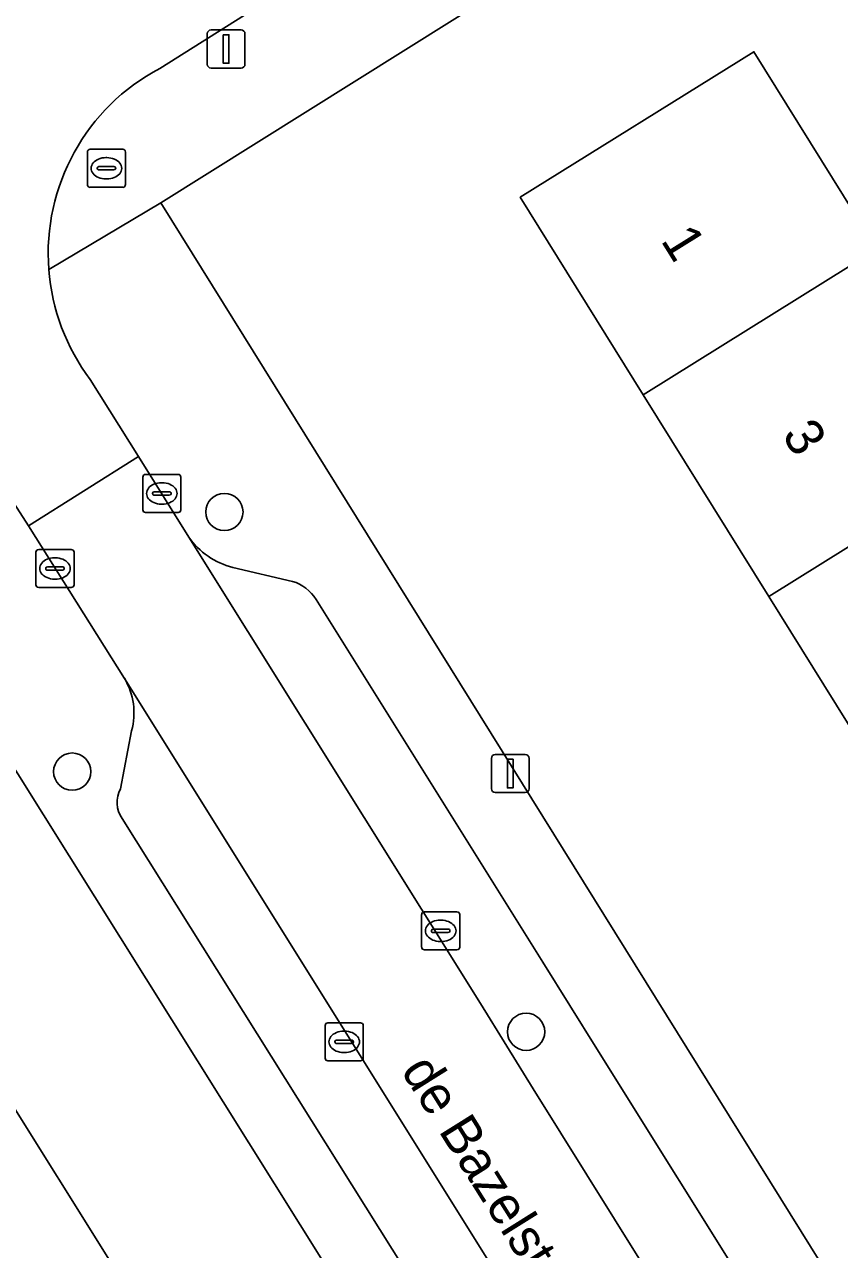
# Model space of a CAD drawing. Extents: x 159352 to 160617, y 385888 to 387323.
# Drawn here: x 159682.11 to 159703.51, y 386145.65 to 386177.82 of the extents above; entities that cross this region are included whole.
import ezdxf

# ---------------------------------------------------------------- set-up
doc = ezdxf.new("R2010")
doc.units = 0
for name, color, linetype in [('IMGEO_Boom', 7, 'Continuous'), ('IMGEO_Brandkraan', 7, 'Continuous'), ('IMGEO_Erf', 7, 'Continuous'), ('IMGEO_Kolk', 7, 'Continuous'), ('IMGEO_Lichtmast', 7, 'Continuous'), ('IMGEO_Openbare_ruimte_label', 7, 'Continuous'), ('IMGEO_Pand', 7, 'Continuous'), ('IMGEO_Pand_nummerreeks', 7, 'Continuous'), ('IMGEO_Parkeervlak_open', 7, 'Continuous'), ('IMGEO_Rijbaan_lokaal_open', 7, 'Continuous'), ('IMGEO_Voetpad_open', 7, 'Continuous')]:
    doc.layers.add(name, color=color, linetype=linetype)

msp = doc.modelspace()

# ---------------------------------------------------------------- linework, layer by layer
at = {"layer": 'IMGEO_Boom'}
for centre in [(159687.358, 386165.017), (159683.361, 386158.199), (159695.28, 386151.366)]:
    msp.add_circle(centre, 0.489, dxfattribs=at)
at = {"layer": 'IMGEO_Brandkraan'}
for p, q in [((159683.76, 386173.617), (159683.76, 386174.469)), ((159683.835, 386174.543), (159684.687, 386174.543)), ((159684.761, 386174.469), (159684.761, 386173.617)), ((159684.062, 386174.086), (159684.46, 386174.086)), ((159684.248, 386174.323), (159684.273, 386174.323)), ((159684.019, 386174.037), (159684.019, 386174.049)), ((159684.457, 386174), (159684.059, 386174)), ((159684.271, 386173.763), (159684.246, 386173.763)), ((159684.503, 386174.049), (159684.503, 386174.037)), ((159684.687, 386173.543), (159683.835, 386173.543))]:
    msp.add_line(p, q, dxfattribs=at)
for points in [[(159683.76, 386173.617), (159683.76, 386174.469)], [(159683.835, 386174.543), (159684.687, 386174.543)], [(159684.761, 386174.469), (159684.761, 386173.617)], [(159684.687, 386173.543), (159683.835, 386173.543)]]:
    msp.add_lwpolyline(points, dxfattribs=at)
for centre, radius, start, end in [((159683.837, 386174.467), 0.0765, 91.552, 178.448), ((159683.837, 386174.467), 0.0765, 91.552, 178.448), ((159684.685, 386174.467), 0.0765, 1.552, 88.448), ((159684.685, 386174.467), 0.0765, 1.552, 88.448), ((159684.059, 386174.046), 0.0403, 85.8775, 175.7526), ((159684.464, 386174.048), 0.0386, 1.7309, 96.639), ((159684.056, 386174.036), 0.0366, 178.938, 274.7102), ((159684.46, 386174.043), 0.043, 264.8664, 352.4533), ((159683.837, 386173.619), 0.0765, 181.552, 268.448), ((159683.837, 386173.619), 0.0765, 181.552, 268.448), ((159684.685, 386173.619), 0.0765, 271.552, 358.448), ((159684.685, 386173.619), 0.0765, 271.552, 358.448)]:
    msp.add_arc(centre, radius, start, end, dxfattribs=at)
for centre, major_axis, ratio, start_param, end_param in [((159684.247, 386174.043), (-0.387, 0.002), 0.722429, 4.712389, 7.853982), ((159684.272, 386174.043), (-0.39, 0.002), 0.717154, 1.570796, 4.712389)]:
    msp.add_ellipse(centre, major_axis=major_axis, ratio=ratio, start_param=start_param, end_param=end_param, dxfattribs=at)
at = {"layer": 'IMGEO_Erf'}
for points in [[(159733.216, 386143.666), (159731.929, 386145.722), (159730.642, 386147.777), (159733.744, 386149.721), (159730.165, 386155.842), (159726.781, 386153.737), (159725.367, 386156.01), (159722.148, 386161.186), (159725.532, 386163.291), (159723.428, 386166.327), (159720.325, 386164.383), (159719.037, 386166.44), (159717.751, 386168.494), (159720.853, 386170.438), (159718.998, 386173.467), (159715.904, 386171.529), (159712.527, 386176.922), (159715.626, 386178.852), (159715.021, 386179.818), (159711.398, 386177.548), (159706.136, 386185.947), (159685.685, 386173.135), (159722.272, 386114.357)], [(159704.872, 386157.62), (159701.649, 386162.8), (159698.354, 386168.096), (159695.125, 386173.284), (159701.262, 386177.103), (159703.904, 386172.858)], [(159712.934, 386108.61), (159677.208, 386165.677), (159674.448, 386166.054), (159663.861, 386159.423), (159663.923, 386159.326), (159657.127, 386155.101), (159662.969, 386145.784), (159661.381, 386144.772)], [(159678.55, 386141.18), (159675.326, 386146.356), (159673.029, 386144.926), (159671.294, 386147.714), (159673.587, 386149.149), (159672.103, 386151.532), (159669.661, 386150.002), (159664.466, 386158.268), (159669.886, 386161.642), (159671.796, 386158.603), (159674.849, 386160.506), (159675.173, 386159.989), (159675.818, 386160.391), (159677.412, 386157.849), (159676.767, 386157.447), (159678.126, 386155.28), (159681.365, 386150.113), (159684.605, 386144.946)]]:
    msp.add_lwpolyline(points, dxfattribs=at)
at = {"layer": 'IMGEO_Kolk'}
for p, q in [((159685.214, 386165.077), (159685.214, 386165.929)), ((159685.289, 386166.003), (159686.141, 386166.003)), ((159685.702, 386165.783), (159685.727, 386165.783)), ((159686.215, 386165.929), (159686.215, 386165.077)), ((159685.473, 386165.497), (159685.473, 386165.509)), ((159685.911, 386165.46), (159685.513, 386165.46)), ((159685.516, 386165.546), (159685.914, 386165.546)), ((159685.957, 386165.509), (159685.957, 386165.497)), ((159685.725, 386165.223), (159685.7, 386165.223)), ((159686.141, 386165.003), (159685.289, 386165.003)), ((159682.408, 386163.107), (159682.408, 386163.959)), ((159682.483, 386164.033), (159683.335, 386164.033)), ((159682.896, 386163.813), (159682.921, 386163.813)), ((159683.409, 386163.959), (159683.409, 386163.107)), ((159682.667, 386163.527), (159682.667, 386163.539)), ((159683.105, 386163.49), (159682.707, 386163.49)), ((159682.71, 386163.576), (159683.108, 386163.576)), ((159683.151, 386163.539), (159683.151, 386163.527)), ((159682.919, 386163.253), (159682.894, 386163.253)), ((159683.335, 386163.033), (159682.483, 386163.033)), ((159692.537, 386153.591), (159692.537, 386154.443)), ((159692.612, 386154.517), (159693.464, 386154.517)), ((159693.538, 386154.443), (159693.538, 386153.591)), ((159693.025, 386154.297), (159693.05, 386154.297)), ((159692.796, 386154.011), (159692.796, 386154.023)), ((159693.234, 386153.974), (159692.836, 386153.974)), ((159692.839, 386154.06), (159693.237, 386154.06)), ((159693.28, 386154.023), (159693.28, 386154.011)), ((159693.464, 386153.517), (159692.612, 386153.517)), ((159693.048, 386153.737), (159693.023, 386153.737)), ((159690.077, 386151.602), (159690.929, 386151.602)), ((159690.002, 386150.676), (159690.002, 386151.528)), ((159690.49, 386151.382), (159690.515, 386151.382)), ((159691.003, 386151.528), (159691.003, 386150.676)), ((159690.261, 386151.096), (159690.261, 386151.108)), ((159690.699, 386151.059), (159690.301, 386151.059)), ((159690.304, 386151.145), (159690.702, 386151.145)), ((159690.745, 386151.108), (159690.745, 386151.096)), ((159690.929, 386150.602), (159690.077, 386150.602)), ((159690.513, 386150.822), (159690.488, 386150.822))]:
    msp.add_line(p, q, dxfattribs=at)
for points in [[(159685.214, 386165.077), (159685.214, 386165.929)], [(159685.289, 386166.003), (159686.141, 386166.003)], [(159686.215, 386165.929), (159686.215, 386165.077)], [(159686.141, 386165.003), (159685.289, 386165.003)], [(159682.408, 386163.107), (159682.408, 386163.959)], [(159682.483, 386164.033), (159683.335, 386164.033)], [(159683.409, 386163.959), (159683.409, 386163.107)], [(159683.335, 386163.033), (159682.483, 386163.033)], [(159692.537, 386153.591), (159692.537, 386154.443)], [(159692.612, 386154.517), (159693.464, 386154.517)], [(159693.538, 386154.443), (159693.538, 386153.591)], [(159693.464, 386153.517), (159692.612, 386153.517)], [(159690.077, 386151.602), (159690.929, 386151.602)], [(159690.002, 386150.676), (159690.002, 386151.528)], [(159691.003, 386151.528), (159691.003, 386150.676)], [(159690.929, 386150.602), (159690.077, 386150.602)]]:
    msp.add_lwpolyline(points, dxfattribs=at)
for centre, radius, start, end in [((159685.291, 386165.927), 0.0765, 91.552, 178.448), ((159685.291, 386165.927), 0.0765, 91.552, 178.448), ((159686.139, 386165.927), 0.0765, 1.552, 88.448), ((159686.139, 386165.927), 0.0765, 1.552, 88.448), ((159685.513, 386165.506), 0.0403, 85.8775, 175.7526), ((159685.51, 386165.496), 0.0366, 178.938, 274.7102), ((159685.914, 386165.503), 0.043, 264.8664, 352.4533), ((159685.918, 386165.508), 0.0386, 1.7309, 96.639), ((159685.291, 386165.079), 0.0765, 181.552, 268.448), ((159685.291, 386165.079), 0.0765, 181.552, 268.448), ((159686.139, 386165.079), 0.0765, 271.552, 358.448), ((159686.139, 386165.079), 0.0765, 271.552, 358.448), ((159682.485, 386163.957), 0.0765, 91.552, 178.448), ((159682.485, 386163.957), 0.0765, 91.552, 178.448), ((159683.333, 386163.957), 0.0765, 1.552, 88.448), ((159683.333, 386163.957), 0.0765, 1.552, 88.448), ((159682.707, 386163.536), 0.0403, 85.8775, 175.7526), ((159682.704, 386163.526), 0.0366, 178.938, 274.7102), ((159683.108, 386163.533), 0.043, 264.8664, 352.4533), ((159683.112, 386163.538), 0.0386, 1.7309, 96.639), ((159682.485, 386163.109), 0.0765, 181.552, 268.448), ((159682.485, 386163.109), 0.0765, 181.552, 268.448), ((159683.333, 386163.109), 0.0765, 271.552, 358.448), ((159683.333, 386163.109), 0.0765, 271.552, 358.448), ((159692.614, 386154.441), 0.0765, 91.552, 178.448), ((159692.614, 386154.441), 0.0765, 91.552, 178.448), ((159693.462, 386154.441), 0.0765, 1.552, 88.448), ((159693.462, 386154.441), 0.0765, 1.552, 88.448), ((159692.836, 386154.02), 0.0403, 85.8775, 175.7526), ((159692.833, 386154.01), 0.0366, 178.938, 274.7102), ((159693.237, 386154.017), 0.043, 264.8664, 352.4533), ((159693.241, 386154.022), 0.0386, 1.7309, 96.639), ((159692.614, 386153.593), 0.0765, 181.552, 268.448), ((159692.614, 386153.593), 0.0765, 181.552, 268.448), ((159693.462, 386153.593), 0.0765, 271.552, 358.448), ((159693.462, 386153.593), 0.0765, 271.552, 358.448), ((159690.079, 386151.526), 0.0765, 91.552, 178.448), ((159690.079, 386151.526), 0.0765, 91.552, 178.448), ((159690.927, 386151.526), 0.0765, 1.552, 88.448), ((159690.927, 386151.526), 0.0765, 1.552, 88.448), ((159690.301, 386151.105), 0.0403, 85.8775, 175.7526), ((159690.298, 386151.095), 0.0366, 178.938, 274.7102), ((159690.702, 386151.102), 0.043, 264.8664, 352.4533), ((159690.706, 386151.107), 0.0386, 1.7309, 96.639), ((159690.079, 386150.678), 0.0765, 181.552, 268.448), ((159690.079, 386150.678), 0.0765, 181.552, 268.448), ((159690.927, 386150.678), 0.0765, 271.552, 358.448), ((159690.927, 386150.678), 0.0765, 271.552, 358.448)]:
    msp.add_arc(centre, radius, start, end, dxfattribs=at)
for centre, major_axis, ratio, start_param, end_param in [((159685.701, 386165.503), (-0.387, 0.002), 0.722429, 4.712389, 7.853982), ((159685.726, 386165.503), (-0.39, 0.002), 0.717154, 1.570796, 4.712389), ((159682.895, 386163.533), (-0.387, 0.002), 0.722429, 4.712389, 7.853982), ((159682.92, 386163.533), (-0.39, 0.002), 0.717154, 1.570796, 4.712389), ((159693.024, 386154.017), (-0.387, 0.002), 0.722429, 4.712389, 7.853982), ((159693.049, 386154.017), (-0.39, 0.002), 0.717154, 1.570796, 4.712389), ((159690.489, 386151.102), (-0.387, 0.002), 0.722429, 4.712389, 7.853982), ((159690.514, 386151.102), (-0.39, 0.002), 0.717154, 1.570796, 4.712389)]:
    msp.add_ellipse(centre, major_axis=major_axis, ratio=ratio, start_param=start_param, end_param=end_param, dxfattribs=at)
at = {"layer": 'IMGEO_Lichtmast'}
for p, q in [((159687.008, 386177.676), (159687.798, 386177.676)), ((159687.798, 386177.676), (159687.008, 386177.676)), ((159686.908, 386176.776), (159686.908, 386177.576)), ((159686.908, 386177.576), (159686.908, 386176.776)), ((159687.898, 386177.576), (159687.898, 386176.776)), ((159687.898, 386176.776), (159687.898, 386177.576)), ((159687.798, 386176.676), (159687.008, 386176.676)), ((159687.008, 386176.676), (159687.798, 386176.676)), ((159694.468, 386158.647), (159695.258, 386158.647)), ((159695.258, 386158.647), (159694.468, 386158.647)), ((159694.368, 386157.747), (159694.368, 386158.547)), ((159694.368, 386158.547), (159694.368, 386157.747)), ((159695.358, 386158.547), (159695.358, 386157.747)), ((159695.358, 386157.747), (159695.358, 386158.547)), ((159695.258, 386157.647), (159694.468, 386157.647)), ((159694.468, 386157.647), (159695.258, 386157.647))]:
    msp.add_line(p, q, dxfattribs=at)
for points in [[(159687.328, 386177.551), (159687.478, 386177.551), (159687.478, 386176.801), (159687.328, 386176.801), (159687.328, 386177.551)], [(159694.788, 386158.522), (159694.938, 386158.522), (159694.938, 386157.772), (159694.788, 386157.772), (159694.788, 386158.522)]]:
    msp.add_lwpolyline(points, dxfattribs=at)
for centre, start, end in [((159687.008, 386177.576), 90, 180), ((159687.008, 386177.576), 90, 180), ((159687.798, 386177.576), 0, 90), ((159687.798, 386177.576), 360, 90), ((159687.008, 386176.776), 180, 270), ((159687.008, 386176.776), 180, 270), ((159687.798, 386176.776), 270, 0), ((159687.798, 386176.776), 270, 0), ((159694.468, 386158.547), 90, 180), ((159694.468, 386158.547), 90, 180), ((159695.258, 386158.547), 0, 90), ((159695.258, 386158.547), 360, 90), ((159694.468, 386157.747), 180, 270), ((159694.468, 386157.747), 180, 270), ((159695.258, 386157.747), 270, 0), ((159695.258, 386157.747), 270, 0)]:
    msp.add_arc(centre, 0.1, start, end, dxfattribs=at)
at = {"layer": 'IMGEO_Pand'}
for points in [[(159704.49, 386171.917), (159703.904, 386172.858), (159701.262, 386177.103), (159695.125, 386173.284), (159698.354, 386168.096)], [(159707.785, 386166.62), (159704.49, 386171.917), (159698.354, 386168.096), (159701.649, 386162.8)], [(159701.649, 386162.8), (159704.872, 386157.62), (159711.009, 386161.441), (159707.785, 386166.62)], [(159675.326, 386146.356), (159678.55, 386141.18), (159684.605, 386144.946), (159681.365, 386150.113)]]:
    msp.add_lwpolyline(points, close=True, dxfattribs=at)
at = {"layer": 'IMGEO_Parkeervlak_open'}
for points in [[(159686.42, 386164.358), (159694.078, 386152.113)], [(159689.145, 386163.195), (159687.581, 386163.56)], [(159695.716, 386153.19), (159689.763, 386162.72)], [(159729.424, 386089.133), (159684.734, 386160.648)], [(159684.921, 386159.27), (159684.627, 386157.743)], [(159684.676, 386156.971), (159692.133, 386145.07)], [(159697.136, 386150.917), (159695.716, 386153.19)], [(159694.078, 386152.113), (159695.462, 386149.864)], [(159701.414, 386144.069), (159697.136, 386150.917)], [(159695.462, 386149.864), (159699.735, 386143.025)]]:
    msp.add_lwpolyline(points, dxfattribs=at)
for centre, radius, start, end in [((159688.078, 386165.527), 2.029, 215.182, 255.8135), ((159688.824, 386162.138), 1.105, 31.8038, 73.1038), ((159683.196, 386159.738), 1.787, 344.835, 30.6211), ((159685.27, 386157.396), 0.731, 151.6824, 215.5811)]:
    msp.add_arc(centre, radius, start, end, dxfattribs=at)
at = {"layer": 'IMGEO_Rijbaan_lokaal_open'}
for points in [[(159685.663, 386176.667), (159690.037, 386179.433), (159686.801, 386184.624), (159667.269, 386172.261), (159670.441, 386167.202), (159673.365, 386168.979)], [(159680.899, 386166.685), (159682.211, 386164.651), (159685.102, 386166.476), (159683.833, 386168.497)]]:
    msp.add_lwpolyline(points, dxfattribs=at)
msp.add_lwpolyline([(159706.934, 386131.508), (159705.576, 386133.684), (159700.717, 386141.456), (159699.735, 386143.025), (159695.462, 386149.864), (159694.078, 386152.113), (159686.42, 386164.358), (159685.102, 386166.476), (159682.211, 386164.651), (159684.734, 386160.648), (159729.424, 386089.133), (159732.198, 386090.885), (159732.063, 386091.102), (159713.32, 386121.238), (159712.101, 386123.199)], close=True, dxfattribs=at)
for centre, radius, start, end in [((159688.233, 386171.802), 5.502, 117.8495, 184.3567), ((159688.244, 386171.804), 5.513, 184.371, 216.8585)]:
    msp.add_arc(centre, radius, start, end, dxfattribs=at)
at = {"layer": 'IMGEO_Voetpad_open'}
for points in [[(159731.871, 386205.614), (159728.58, 386203.569), (159713.085, 386193.866), (159713.589, 386193.057), (159710.577, 386191.178), (159710.076, 386191.982), (159690.037, 386179.433), (159685.663, 386176.667)], [(159682.747, 386171.384), (159685.685, 386173.135), (159706.136, 386185.947), (159706.086, 386186.026), (159709.709, 386188.295), (159709.758, 386188.216), (159711.363, 386189.221), (159714.574, 386191.233), (159731.071, 386201.577)], [(159685.685, 386173.135), (159682.747, 386171.384)], [(159734.961, 386087.237), (159738.007, 386089.077), (159723.212, 386112.846), (159722.272, 386114.357), (159685.685, 386173.135)], [(159678.601, 386168.796), (159674.448, 386166.054), (159677.208, 386165.677), (159712.934, 386108.61), (159713.923, 386107.031), (159717.083, 386101.983), (159727.834, 386084.857), (159727.06, 386082.254), (159731.503, 386085.122)], [(159683.833, 386168.497), (159685.102, 386166.476), (159686.42, 386164.358)], [(159682.211, 386164.651), (159680.899, 386166.685)], [(159684.734, 386160.648), (159682.211, 386164.651)], [(159687.581, 386163.56), (159689.145, 386163.195)], [(159689.763, 386162.72), (159695.716, 386153.19), (159697.136, 386150.917), (159701.414, 386144.069), (159702.412, 386142.47), (159707.231, 386134.755), (159708.615, 386132.541), (159713.768, 386124.242), (159714.974, 386122.307), (159718.917, 386115.978), (159719.286, 386116.213), (159721.153, 386113.232), (159720.775, 386113.01), (159732.147, 386094.729)], [(159684.627, 386157.743), (159684.921, 386159.27)], [(159692.745, 386144.645), (159692.133, 386145.07), (159684.676, 386156.971)]]:
    msp.add_lwpolyline(points, dxfattribs=at)
for centre, radius, start, end in [((159688.233, 386171.802), 5.502, 117.8495, 184.3567), ((159688.244, 386171.804), 5.513, 184.371, 216.8585), ((159688.078, 386165.527), 2.029, 215.182, 255.8135), ((159688.824, 386162.138), 1.105, 31.8038, 73.1038), ((159683.196, 386159.738), 1.787, 344.835, 30.6211), ((159685.27, 386157.396), 0.731, 151.6824, 215.5811)]:
    msp.add_arc(centre, radius, start, end, dxfattribs=at)

# ---------------------------------------------------------------- texts
at = {"layer": 'IMGEO_Openbare_ruimte_label'}
msp.add_text('de Bazelstraat', height=1, rotation=302.0539, dxfattribs=at).set_placement((159691.978, 386150.345))
at = {"layer": 'IMGEO_Pand_nummerreeks'}
for s, p in [('1', (159698.799, 386172.15)), ('3', (159701.978, 386167.042))]:
    msp.add_text(s, height=1, rotation=301.8931, dxfattribs=at).set_placement(p)

doc.saveas('drawing.dxf')
